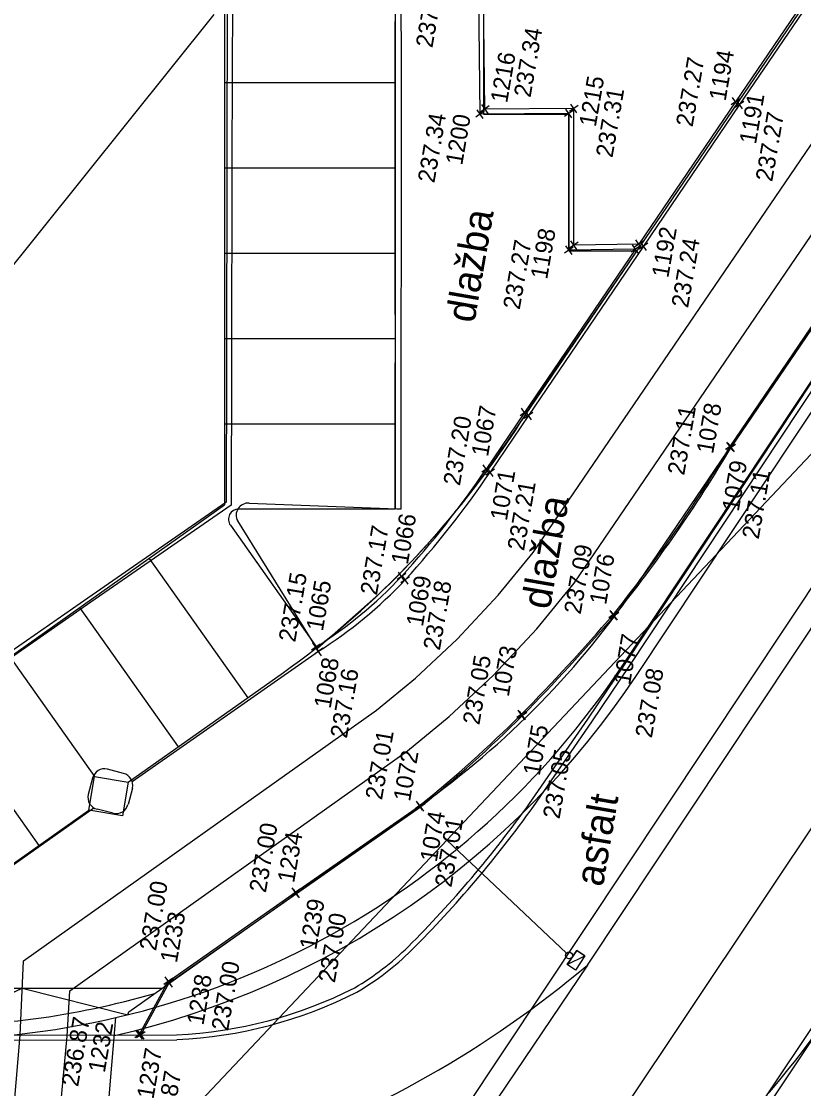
# Model space of a CAD drawing. Extents: x -264205 to -263659, y -1242401 to -1241986.
# Drawn here: x -263813.03 to -263790.1, y -1242302.92 to -1242271.65 of the extents above; entities that cross this region are included whole.
import ezdxf

# ---------------------------------------------------------------- set-up
doc = ezdxf.new("R2010")
doc.units = 0
for name, color, linetype in [('BOD_CISLO_2-4', 7, 'Continuous'), ('BOD_SYMBOL_2-4', 7, 'Continuous'), ('BOD_VYSKA_2-4', 7, 'Continuous'), ('POPIS_2-4', 7, 'Continuous'), ('PROJEKT_OBRUBNIKY_KOMUNIKACIE', 7, 'Continuous'), ('PROJEKT_TDZ_VODOROVNE', 7, 'Continuous'), ('SITUACIA_DSP_2D', 7, 'Continuous'), ('SO_20-1_OBRUBNIKY_DOLNA_HRANA', 7, 'Continuous'), ('SO_20-1_OBRUBNIKY_HORNA_HRANA', 7, 'Continuous'), ('SO_20-2_OBRUBNIKY_DOLNA_HRANA', 7, 'Continuous'), ('SO_20-2_OBRUBNIKY_HORNA_HRANA', 7, 'Continuous'), ('SO_20-4_OBRUBNIKY_HORNA_HRANA', 7, 'Continuous')]:
    doc.layers.add(name, color=color, linetype=linetype)

msp = doc.modelspace()

# ---------------------------------------------------------------- linework, layer by layer
at = {"layer": 'BOD_SYMBOL_2-4'}
for p, q in [((-263792.005, -1242274.138), (-263792.185, -1242273.882)), ((-263799.311, -1242274.132), (-263799.567, -1242274.312)), ((-263799.349, -1242274.35), (-263799.529, -1242274.094)), ((-263796.706, -1242274.117), (-263796.962, -1242274.297)), ((-263796.744, -1242274.335), (-263796.924, -1242274.079)), ((-263791.967, -1242273.92), (-263792.223, -1242274.1)), ((-263791.848, -1242274.001), (-263792.104, -1242274.181)), ((-263791.886, -1242274.219), (-263792.066, -1242273.963)), ((-263799.451, -1242274.28), (-263799.707, -1242274.46)), ((-263799.489, -1242274.498), (-263799.669, -1242274.242)), ((-263796.852, -1242274.262), (-263797.108, -1242274.442)), ((-263796.89, -1242274.48), (-263797.07, -1242274.224)), ((-263796.886, -1242278.488), (-263797.066, -1242278.232)), ((-263796.704, -1242278.122), (-263796.96, -1242278.302)), ((-263796.742, -1242278.34), (-263796.922, -1242278.084)), ((-263794.899, -1242278.236), (-263795.155, -1242278.416)), ((-263794.937, -1242278.454), (-263795.117, -1242278.198)), ((-263794.799, -1242278.089), (-263795.055, -1242278.269)), ((-263794.837, -1242278.307), (-263795.017, -1242278.051)), ((-263794.663, -1242278.148), (-263794.919, -1242278.328)), ((-263794.701, -1242278.366), (-263794.881, -1242278.11)), ((-263796.848, -1242278.27), (-263797.104, -1242278.45)), ((-263798.154, -1242283.028), (-263798.41, -1242283.208)), ((-263798.192, -1242283.246), (-263798.372, -1242282.99)), ((-263798.035, -1242283.111), (-263798.291, -1242283.291)), ((-263798.073, -1242283.329), (-263798.253, -1242283.073)), ((-263792.128, -1242284.02), (-263792.384, -1242284.2)), ((-263792.166, -1242284.238), (-263792.346, -1242283.982)), ((-263792.09, -1242284.046), (-263792.346, -1242284.226)), ((-263792.128, -1242284.264), (-263792.308, -1242284.008)), ((-263799.277, -1242284.686), (-263799.533, -1242284.866)), ((-263799.315, -1242284.904), (-263799.495, -1242284.648)), ((-263799.16, -1242284.771), (-263799.416, -1242284.951)), ((-263799.198, -1242284.989), (-263799.378, -1242284.733)), ((-263801.757, -1242287.828), (-263802.013, -1242288.008)), ((-263801.795, -1242288.046), (-263801.975, -1242287.79)), ((-263801.647, -1242287.923), (-263801.903, -1242288.103)), ((-263801.647, -1242287.923), (-263801.903, -1242288.103)), ((-263801.685, -1242288.141), (-263801.865, -1242287.885)), ((-263801.685, -1242288.141), (-263801.865, -1242287.885)), ((-263795.554, -1242288.948), (-263795.81, -1242289.128)), ((-263795.517, -1242288.977), (-263795.773, -1242289.157)), ((-263795.592, -1242289.166), (-263795.772, -1242288.91)), ((-263795.555, -1242289.195), (-263795.735, -1242288.939)), ((-263804.265, -1242289.897), (-263804.521, -1242290.077)), ((-263804.303, -1242290.115), (-263804.483, -1242289.859)), ((-263804.192, -1242290.02), (-263804.448, -1242290.2)), ((-263804.23, -1242290.238), (-263804.41, -1242289.982)), ((-263798.247, -1242291.873), (-263798.503, -1242292.053)), ((-263798.211, -1242291.902), (-263798.467, -1242292.082)), ((-263798.285, -1242292.091), (-263798.465, -1242291.835)), ((-263798.249, -1242292.12), (-263798.429, -1242291.864)), ((-263801.268, -1242294.761), (-263801.448, -1242294.505)), ((-263801.23, -1242294.543), (-263801.486, -1242294.723)), ((-263801.195, -1242294.575), (-263801.451, -1242294.755)), ((-263801.233, -1242294.793), (-263801.413, -1242294.537)), ((-263804.866, -1242297.081), (-263805.122, -1242297.261)), ((-263804.832, -1242297.115), (-263805.088, -1242297.295)), ((-263804.904, -1242297.299), (-263805.084, -1242297.043)), ((-263804.87, -1242297.333), (-263805.05, -1242297.077)), ((-263808.591, -1242299.689), (-263808.847, -1242299.869)), ((-263808.562, -1242299.728), (-263808.818, -1242299.908)), ((-263808.629, -1242299.907), (-263808.809, -1242299.651)), ((-263808.6, -1242299.946), (-263808.78, -1242299.69)), ((-263809.442, -1242301.256), (-263809.698, -1242301.436)), ((-263809.48, -1242301.474), (-263809.66, -1242301.218)), ((-263809.393, -1242301.256), (-263809.649, -1242301.436)), ((-263809.431, -1242301.474), (-263809.611, -1242301.218))]:
    msp.add_line(p, q, dxfattribs=at)
at = {"layer": 'PROJEKT_OBRUBNIKY_KOMUNIKACIE'}
for p, q in [((-263794.898, -1242288.032), (-263742.736, -1242211.145)), ((-263798.899, -1242284.125), (-263751.864, -1242215.081)), ((-263807.068, -1242270.982), (-263807.068, -1242285.823)), ((-263802.068, -1242280.24), (-263802.068, -1242271.654)), ((-263795.416, -1242290.541), (-263784.213, -1242273.68)), ((-263802.068, -1242285.947), (-263802.068, -1242281.654)), ((-263817.19, -1242292.982), (-263807.068, -1242285.823)), ((-263809.895, -1242293.947), (-263805.344, -1242290.728)), ((-263814.555, -1242297.242), (-263811.05, -1242294.763)), ((-263809.875, -1242300.669), (-263801.342, -1242294.634)), ((-263816.308, -1242299.982), (-263808.904, -1242299.982)), ((-263809.906, -1242300.757), (-263809.875, -1242300.669))]:
    msp.add_line(p, q, dxfattribs=at)
for points in [[(-263798.064, -1242282.882), (-263794.987, -1242278.383), (-263796.968, -1242278.382), (-263796.968, -1242274.382), (-263799.468, -1242274.382), (-263799.468, -1242270.382), (-263791.968, -1242270.382), (-263791.968, -1242266.382), (-263796.968, -1242266.382), (-263796.968, -1242260.382), (-263791.968, -1242260.382), (-263791.968, -1242258.382), (-263799.468, -1242258.382), (-263799.468, -1242265.987), (-263802.068, -1242265.987)], [(-263802.068, -1242265.987), (-263802.068, -1242270.24), (-263802.068, -1242270.947), (-263802.068, -1242271.654), (-263802.068, -1242273.447), (-263802.068, -1242275.947), (-263802.068, -1242278.447), (-263802.068, -1242280.24), (-263802.068, -1242281.654), (-263802.068, -1242283.447), (-263802.068, -1242285.947), (-263806.656, -1242285.943)], [(-263806.901, -1242286.416), (-263804.349, -1242290.024), (-263802.552, -1242288.44)], [(-263810.881, -1242293.778), (-263809.895, -1242293.947), (-263810.064, -1242294.932), (-263811.05, -1242294.763), (-263810.881, -1242293.778)], [(-263816.327, -1242301.51), (-263813.002, -1242299.982), (-263809.906, -1242300.757)]]:
    msp.add_lwpolyline(points, dxfattribs=at)
for centre, radius, start, end in [((-263821.806, -1242268.304), 27.86, 313.7192, 328.4502), ((-263820.069, -1242269.909), 25.5, 305.2702, 326.1165), ((-263806.656, -1242286.243), 0.3, 89.9436, 215.2702), ((-263816.067, -1242273.815), 25.5, 305.2702, 326.1165), ((-263815.822, -1242276.982), 24.5, 270, 326.3992)]:
    msp.add_arc(centre, radius, start, end, dxfattribs=at)
at = {"layer": 'PROJEKT_TDZ_VODOROVNE'}
for p, q in [((-263807.068, -1242273.447), (-263802.068, -1242273.447)), ((-263796.435, -1242299.302), (-263779.243, -1242273.429)), ((-263795, -1242290.817), (-263783.807, -1242273.971)), ((-263807.068, -1242275.947), (-263802.068, -1242275.947)), ((-263807.068, -1242278.447), (-263802.068, -1242278.447)), ((-263807.068, -1242280.947), (-263802.068, -1242280.947)), ((-263807.068, -1242283.447), (-263802.068, -1242283.447)), ((-263809.278, -1242287.386), (-263806.39, -1242291.468)), ((-263811.319, -1242288.829), (-263808.432, -1242292.912)), ((-263813.36, -1242290.273), (-263810.881, -1242293.778)), ((-263813.36, -1242290.273), (-263810.881, -1242293.778)), ((-263815.401, -1242291.717), (-263812.514, -1242295.799)), ((-263824.083, -1242346.553), (-263789.385, -1242294.564)), ((-263786.678, -1242296.363), (-263806.091, -1242325.442)), ((-263786.512, -1242296.474), (-263805.925, -1242325.553)), ((-263796.435, -1242299.302), (-263802.558, -1242308.383)), ((-263810.915, -1242308.545), (-263810.255, -1242300.841))]:
    msp.add_line(p, q, dxfattribs=at)
for points in [[(-263831.211, -1242326.873), (-263816.19, -1242319.41), (-263814.291, -1242315.804), (-263813.06, -1242301.353), (-263812.968, -1242299.181), (-263802.618, -1242291.831), (-263801.478, -1242290.893), (-263800.257, -1242289.755), (-263799.049, -1242288.464), (-263798.027, -1242287.218), (-263749.798, -1242216.488), (-263742.736, -1242211.145)], [(-263830.6, -1242328.105), (-263815.26, -1242320.378), (-263813.062, -1242316.188), (-263811.682, -1242301.389), (-263811.608, -1242300.055), (-263801.705, -1242293.023), (-263800.489, -1242292.021), (-263799.197, -1242290.817), (-263797.92, -1242289.454), (-263796.825, -1242288.118), (-263748.697, -1242217.536), (-263741.831, -1242212.341)]]:
    msp.add_lwpolyline(points, dxfattribs=at)
for centre, radius, start, end in [((-263815.822, -1242276.982), 25, 282.7622, 326.3992), ((-263816.477, -1242275.476), 31.135, 289.1139, 310.0684), ((-263809.228, -1242287.295), 24, 270.4085, 326.3969)]:
    msp.add_arc(centre, radius, start, end, dxfattribs=at)
at = {"layer": 'SITUACIA_DSP_2D'}
for p, q in [((-263822.88, -1242337.914), (-263734.49, -1242204.937)), ((-263794.898, -1242288.032), (-263742.736, -1242211.145)), ((-263798.899, -1242284.125), (-263751.864, -1242215.081)), ((-263807.38, -1242271.45), (-263817.128, -1242283.593)), ((-263802.068, -1242280.24), (-263802.068, -1242271.654)), ((-263795.416, -1242290.541), (-263784.214, -1242273.68)), ((-263780.353, -1242274.236), (-263808.248, -1242303.783)), ((-263802.068, -1242285.947), (-263802.068, -1242281.654)), ((-263809.895, -1242293.947), (-263805.344, -1242290.728)), ((-263811.05, -1242294.763), (-263810.881, -1242293.778)), ((-263810.881, -1242293.778), (-263809.895, -1242293.947)), ((-263809.895, -1242293.947), (-263810.064, -1242294.932)), ((-263814.555, -1242297.242), (-263811.05, -1242294.763)), ((-263810.064, -1242294.932), (-263811.05, -1242294.763)), ((-263809.875, -1242300.669), (-263801.342, -1242294.634)), ((-263797.048, -1242298.952), (-263800.558, -1242295.638)), ((-263797.029, -1242299.286), (-263796.75, -1242298.871)), ((-263796.75, -1242298.871), (-263797.029, -1242299.286)), ((-263796.75, -1242298.871), (-263796.51, -1242299.032)), ((-263796.51, -1242299.032), (-263796.75, -1242298.871)), ((-263797.029, -1242299.286), (-263796.51, -1242299.032)), ((-263797.029, -1242299.286), (-263796.51, -1242299.032)), ((-263796.51, -1242299.032), (-263796.788, -1242299.448)), ((-263796.788, -1242299.448), (-263797.029, -1242299.286)), ((-263816.327, -1242301.51), (-263813.002, -1242299.982)), ((-263816.308, -1242299.982), (-263808.904, -1242299.982)), ((-263813.002, -1242299.982), (-263809.906, -1242300.757)), ((-263809.906, -1242300.757), (-263809.875, -1242300.669))]:
    msp.add_line(p, q, dxfattribs=at)
for points in [[(-263798.064, -1242282.882), (-263794.987, -1242278.383), (-263796.968, -1242278.382), (-263796.968, -1242274.382), (-263799.468, -1242274.382), (-263799.468, -1242270.382), (-263791.968, -1242270.382), (-263791.968, -1242266.382), (-263796.968, -1242266.382), (-263796.968, -1242260.382), (-263791.968, -1242260.382), (-263791.968, -1242258.382), (-263799.468, -1242258.382), (-263799.468, -1242265.987), (-263802.068, -1242265.987)], [(-263802.068, -1242265.987), (-263802.068, -1242270.24), (-263802.068, -1242270.947), (-263802.068, -1242271.654), (-263802.068, -1242273.447), (-263802.068, -1242275.947), (-263802.068, -1242278.447), (-263802.068, -1242280.24), (-263802.068, -1242280.24), (-263802.068, -1242281.654), (-263802.068, -1242283.447), (-263802.068, -1242285.947), (-263806.656, -1242285.943)], [(-263806.901, -1242286.416), (-263804.349, -1242290.024), (-263802.552, -1242288.44)]]:
    msp.add_lwpolyline(points, dxfattribs=at)
msp.add_circle((-263796.975, -1242299.02), 0.1, dxfattribs=at)
for centre, radius, start, end in [((-263821.806, -1242268.304), 27.86, 313.7192, 328.4502), ((-263820.069, -1242269.909), 25.5, 305.2702, 326.1165), ((-263806.656, -1242286.243), 0.3, 89.9436, 215.2702), ((-263816.067, -1242273.815), 25.5, 305.2702, 326.1165), ((-263815.822, -1242276.982), 24.5, 270, 326.3992), ((-263815.836, -1242276.967), 24.119, 268.8787, 286.1798)]:
    msp.add_arc(centre, radius, start, end, dxfattribs=at)
at = {"layer": 'SO_20-1_OBRUBNIKY_DOLNA_HRANA'}
for points in [[(-263798.013, -1242294.654), (-263796.303, -1242292.18), (-263795.189, -1242290.524), (-263793.538, -1242288.034), (-263790.216, -1242283.022), (-263787.462, -1242278.872), (-263784.7, -1242274.704)], [(-263816.42, -1242301.504), (-263808.465, -1242301.488)]]:
    msp.add_lwpolyline(points, dxfattribs=at)
for centre, major_axis, ratio, start_param, end_param in [((-263825.45, -1242274.928), (18.854, 28.266), 0.994545, 4.514508, 4.677485), ((-263807.174, -1242293.246), (7.914, -0.383), 0.999893, 5.287754, 5.542292), ((-263809.043, -1242288.645), (12.659, 2.536), 0.995625, 4.560279, 4.986171)]:
    msp.add_ellipse(centre, major_axis=major_axis, ratio=ratio, start_param=start_param, end_param=end_param, dxfattribs=at)
at = {"layer": 'SO_20-1_OBRUBNIKY_HORNA_HRANA'}
for points in [[(-263798.132, -1242294.573), (-263796.423, -1242292.099), (-263795.31, -1242290.444), (-263793.659, -1242287.955), (-263790.34, -1242282.948), (-263787.584, -1242278.79), (-263784.82, -1242274.623)], [(-263816.413, -1242301.358), (-263808.476, -1242301.344)]]:
    msp.add_lwpolyline(points, dxfattribs=at)
for centre, major_axis, ratio, start_param, end_param in [((-263824.958, -1242275.34), (19.218, 27.206), 0.990974, 4.5401, 4.705457), ((-263807.23, -1242293.156), (3.846, 6.885), 0.999705, 4.179295, 4.429956), ((-263809.03, -1242288.701), (12.476, 2.408), 0.995918, 4.56612, 4.994215)]:
    msp.add_ellipse(centre, major_axis=major_axis, ratio=ratio, start_param=start_param, end_param=end_param, dxfattribs=at)
at = {"layer": 'SO_20-2_OBRUBNIKY_DOLNA_HRANA'}
for points in [[(-263806.994, -1242271.026), (-263807.002, -1242275.743), (-263807.011, -1242281.745), (-263807.02, -1242285.741), (-263807.029, -1242285.754), (-263811.073, -1242288.555), (-263815.133, -1242291.369), (-263816.759, -1242292.501), (-263817.492, -1242292.982)], [(-263806.84, -1242270.884), (-263806.855, -1242275.745), (-263806.866, -1242281.754), (-263806.878, -1242285.825), (-263810.985, -1242288.673), (-263815.032, -1242291.478), (-263816.678, -1242292.619), (-263817.431, -1242293.129)]]:
    msp.add_lwpolyline(points, dxfattribs=at)
at = {"layer": 'SO_20-2_OBRUBNIKY_HORNA_HRANA'}
for p, q in [((-263810.031, -1242293.692), (-263810.506, -1242293.563)), ((-263810.938, -1242293.824), (-263811.066, -1242294.305)), ((-263809.77, -1242294.115), (-263809.9, -1242294.594)), ((-263810.337, -1242294.853), (-263810.802, -1242294.734))]:
    msp.add_line(p, q, dxfattribs=at)
for points in [[(-263806.349, -1242285.768), (-263802.019, -1242285.94), (-263801.893, -1242285.938), (-263801.891, -1242280.951), (-263801.886, -1242277.952), (-263801.882, -1242272.951), (-263801.89, -1242270.939), (-263802.035, -1242270.942), (-263805.994, -1242270.993), (-263806.398, -1242270.99)], [(-263809.779, -1242293.921), (-263804.32, -1242290.11), (-263804.578, -1242289.676), (-263806.686, -1242286.292)], [(-263816.857, -1242293.981), (-263814.551, -1242297.238), (-263814.147, -1242296.981), (-263810.898, -1242294.697)]]:
    msp.add_lwpolyline(points, dxfattribs=at)
for centre, major_axis, ratio, start_param, end_param in [((-263806.378, -1242286.12), (-0.146, -0.321), 0.999003, 3.486151, 5.650017), ((-263810.591, -1242293.91), (-0.323, -0.152), 0.999281, 4.032527, 5.601655), ((-263810.111, -1242294.033), (-0.104, 0.335), 0.999708, 4.176421, 5.753618), ((-263810.725, -1242294.391), (-0.16, -0.313), 0.999933, 4.9388, 6.536829), ((-263810.245, -1242294.51), (-0.245, -0.257), 0.998318, 0.49947, 2.091931)]:
    msp.add_ellipse(centre, major_axis=major_axis, ratio=ratio, start_param=start_param, end_param=end_param, dxfattribs=at)
at = {"layer": 'SO_20-4_OBRUBNIKY_HORNA_HRANA'}
for p, q in [((-263788.718, -1242269.04), (-263792.095, -1242274.01)), ((-263788.598, -1242269.122), (-263791.976, -1242274.091)), ((-263799.579, -1242274.37), (-263799.632, -1242270.168)), ((-263799.439, -1242274.222), (-263799.486, -1242270.312)), ((-263792.095, -1242274.01), (-263794.927, -1242278.179)), ((-263791.976, -1242274.091), (-263794.791, -1242278.238)), ((-263796.98, -1242274.352), (-263799.579, -1242274.37)), ((-263796.834, -1242274.207), (-263799.439, -1242274.222)), ((-263796.976, -1242278.36), (-263796.98, -1242274.352)), ((-263796.832, -1242278.212), (-263796.834, -1242274.207)), ((-263794.791, -1242278.238), (-263798.163, -1242283.201)), ((-263794.927, -1242278.179), (-263796.832, -1242278.212)), ((-263795.027, -1242278.326), (-263798.282, -1242283.118)), ((-263795.027, -1242278.326), (-263796.976, -1242278.36)), ((-263792.256, -1242284.11), (-263788.335, -1242278.341)), ((-263792.218, -1242284.136), (-263788.291, -1242278.357)), ((-263798.282, -1242283.118), (-263799.405, -1242284.776)), ((-263798.163, -1242283.201), (-263799.288, -1242284.861)), ((-263804.994, -1242297.171), (-263801.358, -1242294.633)), ((-263804.96, -1242297.205), (-263801.323, -1242294.665)), ((-263808.719, -1242299.779), (-263804.994, -1242297.171)), ((-263808.69, -1242299.818), (-263804.96, -1242297.205)), ((-263809.57, -1242301.346), (-263808.719, -1242299.779)), ((-263809.521, -1242301.346), (-263808.69, -1242299.818))]:
    msp.add_line(p, q, dxfattribs=at)
for centre, major_axis, ratio, start_param, end_param in [((-263829.542, -1242261.832), (21.964, 37.538), 0.998689, 4.565125, 4.703237), ((-263830.013, -1242261.511), (22.866, 37.763), 0.997814, 4.581288, 4.717418), ((-263822.029, -1242269.43), (15.715, 22.664), 0.991237, 4.577303, 4.722574), ((-263822.152, -1242269.355), (14.774, 23.443), 0.996977, 4.533893, 4.678919), ((-263811.206, -1242279.171), (8.573, 9.498), 0.999003, 4.438205, 4.693025), ((-263811.312, -1242279.028), (7.747, 10.574), 0.999578, 4.336891, 4.589134), ((-263840.603, -1242250.481), (43.182, 41.314), 0.99048, 4.743106, 4.80965), ((-263841.305, -1242249.804), (44.07, 41.715), 0.992295, 4.748676, 4.814221), ((-263825.514, -1242264.631), (15.262, 35.374), 0.999717, 4.226891, 4.330857), ((-263825.446, -1242264.742), (37.432, 8.749), 0.999825, 5.161194, 5.265459)]:
    msp.add_ellipse(centre, major_axis=major_axis, ratio=ratio, start_param=start_param, end_param=end_param, dxfattribs=at)

# ---------------------------------------------------------------- texts
at = {"layer": 'BOD_CISLO_2-4'}
for s, p in [('1216', (-263798.789, -1242274.066)), ('1194', (-263792.386, -1242274.006)), ('1215', (-263796.192, -1242274.767)), ('1191', (-263791.496, -1242275.273)), ('1200', (-263800.106, -1242275.888)), ('1198', (-263797.617, -1242279.232)), ('1192', (-263794.065, -1242279.187)), ('1067', (-263799.35, -1242284.426)), ('1078', (-263792.753, -1242284.346)), ('1079', (-263792.002, -1242286.033)), ('1071', (-263798.798, -1242286.304)), ('1066', (-263801.701, -1242287.59)), ('1076', (-263795.888, -1242288.764)), ('1069', (-263801.259, -1242289.407)), ('1065', (-263804.19, -1242289.541)), ('1077', (-263795.188, -1242291.117)), ('1073', (-263798.743, -1242291.461)), ('1068', (-263803.964, -1242291.805)), ('1075', (-263797.834, -1242293.776)), ('1072', (-263801.635, -1242294.527)), ('1074', (-263800.854, -1242296.305)), ('1234', (-263805.034, -1242296.916)), ('1239', (-263804.385, -1242298.874)), ('1233', (-263808.469, -1242299.257)), ('1238', (-263807.691, -1242301.085)), ('1232', (-263810.582, -1242302.476)), ('1237', (-263809.156, -1242303.248))]:
    msp.add_text(s, height=0.5, rotation=80.1724, dxfattribs=at).set_placement(p)
at = {"layer": 'BOD_VYSKA_2-4'}
for s, p in [('237.39', (-263800.98, -1242272.448)), ('237.34', (-263798.104, -1242273.903)), ('237.27', (-263793.354, -1242274.766)), ('237.31', (-263795.702, -1242275.666)), ('237.34', (-263800.922, -1242276.407)), ('237.27', (-263791.02, -1242276.371)), ('237.27', (-263798.421, -1242280.119)), ('237.24', (-263793.487, -1242280.068)), ('237.20', (-263800.174, -1242285.279)), ('237.11', (-263793.6, -1242284.972)), ('237.11', (-263791.416, -1242286.844)), ('237.21', (-263798.295, -1242287.184)), ('237.17', (-263802.606, -1242288.487)), ('237.09', (-263796.634, -1242289.043)), ('237.15', (-263805, -1242289.861)), ('237.18', (-263800.761, -1242290.101)), ('237.05', (-263799.604, -1242292.286)), ('237.16', (-263803.486, -1242292.678)), ('237.08', (-263794.548, -1242292.667)), ('237.01', (-263802.458, -1242294.483)), ('237.05', (-263797.254, -1242295.041)), ('237.01', (-263800.422, -1242297.044)), ('237.00', (-263805.861, -1242297.201)), ('237.00', (-263809.079, -1242298.903)), ('237.00', (-263803.839, -1242299.841)), ('237.00', (-263806.97, -1242301.252)), ('236.87', (-263811.363, -1242302.884)), ('236.87', (-263808.685, -1242304.463))]:
    msp.add_text(s, height=0.5, rotation=80.1724, dxfattribs=at).set_placement(p)
at = {"layer": 'POPIS_2-4'}
for s, p in [('dlažba', (-263799.749, -1242280.513)), ('dlažba', (-263797.535, -1242288.907)), ('asfalt', (-263795.982, -1242297.03))]:
    msp.add_text(s, height=0.8437, rotation=80.1724, dxfattribs=at).set_placement(p)

doc.saveas('drawing.dxf')
